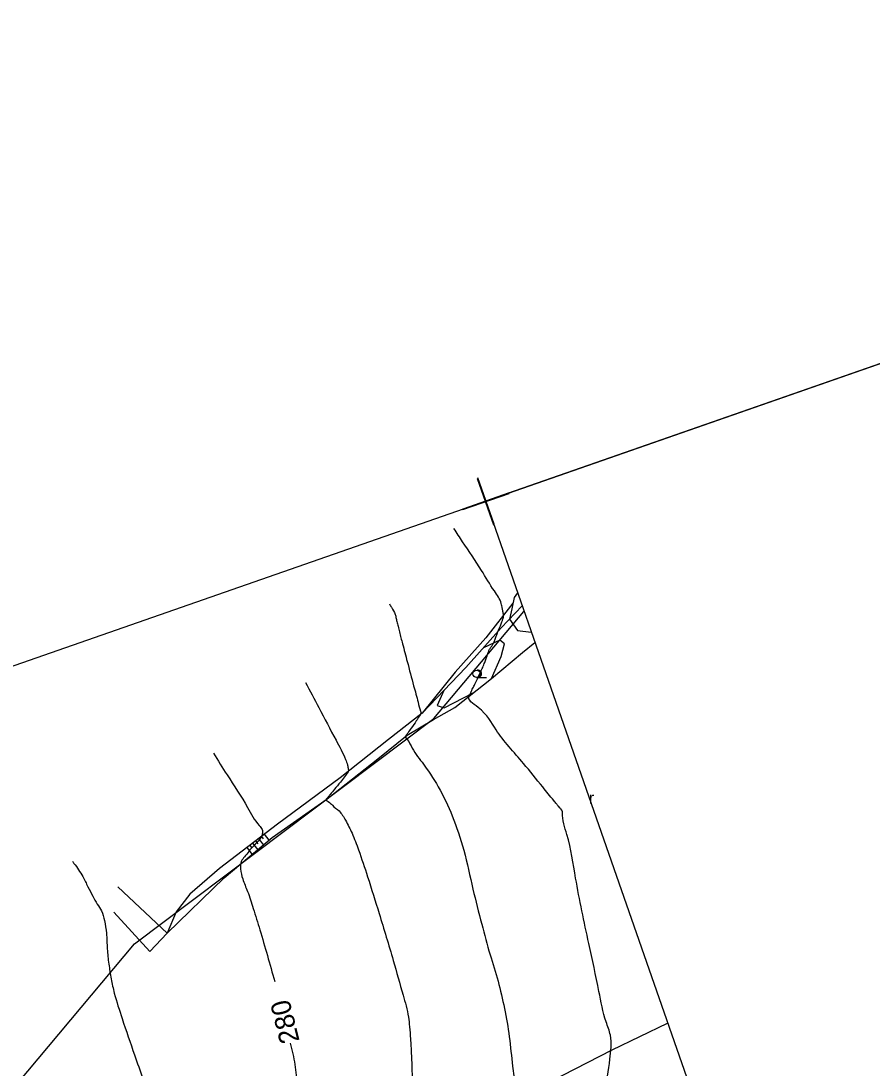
# Model space of a CAD drawing. Extents: x -477701 to -476785, y -1116511 to -1115314.
# Drawn here: x -477510.1 to -477336.7, y -1115532.3 to -1115319.1 of the extents above; entities that cross this region are included whole.
import ezdxf

# ---------------------------------------------------------------- set-up
doc = ezdxf.new("R2010")
doc.units = 0
for name, color, linetype in [('ObPÚ', 7, 'Continuous'), ('razitko', 7, 'Continuous'), ('SVK_STAT', 7, 'Continuous'), ('Vrstevnice_hlavni', 7, 'Continuous'), ('Vrstevnice_popis', 7, 'Continuous'), ('Vrstevnice_vedlejsi', 7, 'Continuous')]:
    doc.layers.add(name, color=color, linetype=linetype)

msp = doc.modelspace()

# ---------------------------------------------------------------- linework, layer by layer
at = {"layer": 'ObPÚ'}
msp.add_lwpolyline([(-477633.61, -1115693.32), (-477565.48, -1115600.75), (-477486.91, -1115507.04), (-477425.98, -1115461.11), (-477407.63, -1115439.32)], dxfattribs=at)
at = {"layer": 'razitko'}
for p, q in [((-477413.76, -1115421.73), (-477417.06, -1115412.29)), ((-477413.76, -1115421.73), (-477417.06, -1115412.29)), ((-477413.71, -1115421.55), (-477417.01, -1115412.11)), ((-477413.71, -1115421.55), (-477417.01, -1115412.11)), ((-477413.71, -1115421.55), (-477417.01, -1115412.11)), ((-477413.71, -1115421.55), (-477417.01, -1115412.11)), ((-477413.71, -1115421.55), (-477417.01, -1115412.11)), ((-477413.71, -1115421.55), (-477417.01, -1115412.11)), ((-477413.71, -1115421.55), (-477417.01, -1115412.11)), ((-477413.71, -1115421.55), (-477417.01, -1115412.11)), ((-477413.71, -1115421.55), (-477417.01, -1115412.11)), ((-477413.71, -1115421.55), (-477417.01, -1115412.11)), ((-477413.71, -1115421.55), (-477417.01, -1115412.11)), ((-477413.71, -1115421.55), (-477417.01, -1115412.11)), ((-477413.71, -1115421.55), (-477417.01, -1115412.11)), ((-477413.71, -1115421.55), (-477417.01, -1115412.11)), ((-477410.69, -1115415.37), (-477420.13, -1115418.66)), ((-477410.69, -1115415.37), (-477420.13, -1115418.66)), ((-477410.64, -1115415.18), (-477420.08, -1115418.47)), ((-477410.64, -1115415.18), (-477420.08, -1115418.47)), ((-477410.64, -1115415.18), (-477420.08, -1115418.47)), ((-477410.64, -1115415.18), (-477420.08, -1115418.47)), ((-477410.64, -1115415.18), (-477420.08, -1115418.47)), ((-477410.64, -1115415.18), (-477420.08, -1115418.47)), ((-477410.64, -1115415.18), (-477420.08, -1115418.47)), ((-477410.64, -1115415.18), (-477420.08, -1115418.47)), ((-477410.64, -1115415.18), (-477420.08, -1115418.47)), ((-477410.64, -1115415.18), (-477420.08, -1115418.47)), ((-477410.64, -1115415.18), (-477420.08, -1115418.47)), ((-477410.64, -1115415.18), (-477420.08, -1115418.47)), ((-477410.64, -1115415.18), (-477420.08, -1115418.47)), ((-477410.64, -1115415.18), (-477420.08, -1115418.47))]:
    msp.add_line(p, q, dxfattribs=at)
for points in [[(-477134.92, -1115319.05), (-476789.2, -1116310.67), (-477350.19, -1116506.26), (-477695.91, -1115514.64)], [(-477134.92, -1115319.05), (-476789.25, -1116310.52), (-477069.69, -1116408.3), (-477415.36, -1115416.83)]]:
    msp.add_lwpolyline(points, close=True, dxfattribs=at)
at = {"layer": 'SVK_STAT'}
for p, q in [((-477417.26, -1115452.77), (-477415.26, -1115452.77)), ((-477460.5, -1115484.69), (-477459.55, -1115485.94)), ((-477463.48, -1115486.97), (-477463.07, -1115487.5)), ((-477462.89, -1115486.51), (-477461.85, -1115487.87)), ((-477462.29, -1115486.06), (-477461.85, -1115486.63)), ((-477461.7, -1115485.6), (-477460.7, -1115486.9)), ((-477461.1, -1115485.15), (-477460.72, -1115485.64)), ((-477464.08, -1115487.43), (-477463, -1115488.83))]:
    msp.add_line(p, q, dxfattribs=at)
for points in [[(-477408.95, -1115435.54), (-477409.65, -1115436.47), (-477410.13, -1115438.8), (-477410.55, -1115440.88), (-477408.93, -1115443.18), (-477406.15, -1115443.58)], [(-477409.89, -1115437.63), (-477415.38, -1115444.67), (-477421.65, -1115451.69), (-477428.38, -1115460.07)], [(-477408.02, -1115438.21), (-477412.25, -1115442.69), (-477419.47, -1115450.75), (-477428.38, -1115460.07), (-477435.24, -1115465.39), (-477445.09, -1115473.25), (-477457.83, -1115482.64), (-477469.63, -1115491.69), (-477475.7, -1115496.9), (-477478.48, -1115500.48), (-477480.32, -1115504.89)], [(-477480.32, -1115504.89), (-477468.68, -1115493.6), (-477458.91, -1115485.4), (-477447.71, -1115477.47), (-477437.37, -1115469.35), (-477431.38, -1115464.51), (-477426.08, -1115461.33), (-477421.68, -1115458.86), (-477414.22, -1115452.98), (-477407.92, -1115447.67), (-477405.43, -1115445.64)], [(-477414.22, -1115452.98), (-477412.29, -1115448.52), (-477411.62, -1115445.94), (-477412.53, -1115445.21), (-477415.86, -1115446.72)], [(-477423.93, -1115455.41), (-477425.28, -1115458.5), (-477423.86, -1115458.97), (-477417.95, -1115455.92)], [(-477491.17, -1115500.56), (-477483.8, -1115508.56), (-477480.32, -1115504.89), (-477490.33, -1115495.45)], [(-477427.86, -1115563.62), (-477422.06, -1115550.46), (-477409.86, -1115539), (-477389.68, -1115528.61), (-477378.39, -1115523.19)]]:
    msp.add_lwpolyline(points, dxfattribs=at)
msp.add_circle((-477417.26, -1115452.02), 0.75, dxfattribs=at)
msp.add_arc((-477417.01, -1115452.02), 0.75, 260.4059, 99.5941, dxfattribs=at)
at = {"layer": 'Vrstevnice_hlavni'}
for points in [[(-477470.88, -1115468.18), (-477468.09, -1115472.63), (-477463.92, -1115479.23), (-477461.54, -1115482.94), (-477460.94, -1115483.75), (-477460.93, -1115484.71), (-477461.5, -1115485.8), (-477462.67, -1115487.04), (-477463.67, -1115488.2), (-477464.52, -1115489.28), (-477465.21, -1115490.27), (-477465.34, -1115491.78), (-477464.91, -1115493.81), (-477463.92, -1115496.35), (-477462.76, -1115499.8), (-477461.42, -1115504.15), (-477458.39, -1115514.68)], [(-477455.25, -1115527.25), (-477454.28, -1115531.61), (-477453.93, -1115535.98), (-477453.71, -1115542.53), (-477453.62, -1115551.27), (-477452.88, -1115560.5), (-477451.47, -1115570.23), (-477449.42, -1115580.46), (-477447.7, -1115588.21), (-477446.32, -1115593.47), (-477445.28, -1115596.25), (-477444.5, -1115598.3), (-477443.99, -1115599.63), (-477443.73, -1115600.22), (-477443.33, -1115600.85), (-477442.79, -1115601.52), (-477442.09, -1115602.23), (-477441.43, -1115602.82), (-477440.8, -1115603.32), (-477440.21, -1115603.7), (-477438, -1115605.12), (-477434.18, -1115607.56), (-477428.74, -1115611.03), (-477424.51, -1115613.85), (-477421.48, -1115616.01), (-477419.66, -1115617.52), (-477417.5, -1115619.22), (-477415.02, -1115621.12), (-477412.2, -1115623.21), (-477409.53, -1115625.29), (-477407, -1115627.35), (-477404.6, -1115629.39), (-477402.88, -1115630.91), (-477401.82, -1115631.93), (-477401.44, -1115632.44), (-477401.06, -1115632.84), (-477400.71, -1115633.14), (-477400.36, -1115633.34), (-477398.97, -1115634.31), (-477396.51, -1115636.06), (-477393.01, -1115638.58), (-477389.76, -1115640.78), (-477386.78, -1115642.66), (-477384.06, -1115644.2), (-477382.21, -1115645.24), (-477381.24, -1115645.78), (-477381.13, -1115645.8), (-477380.99, -1115645.83), (-477380.81, -1115645.87), (-477380.58, -1115645.91), (-477380.45, -1115646.15), (-477380.4, -1115646.61), (-477380.44, -1115647.28), (-477380.32, -1115647.94), (-477380.04, -1115648.6), (-477379.6, -1115649.25), (-477378.81, -1115650.19), (-477377.67, -1115651.41), (-477376.18, -1115652.91), (-477373.49, -1115655.96), (-477369.58, -1115660.54), (-477364.46, -1115666.67), (-477360.7, -1115671.04), (-477358.31, -1115673.66), (-477357.28, -1115674.52), (-477356.2, -1115675.6), (-477355.08, -1115676.92), (-477353.91, -1115678.46), (-477352.08, -1115681.9), (-477349.57, -1115687.23), (-477346.39, -1115694.45), (-477343.98, -1115699.91), (-477342.34, -1115703.6), (-477341.47, -1115705.52), (-477340.85, -1115706.87), (-477340.49, -1115707.65), (-477340.39, -1115707.86), (-477340.31, -1115708.31), (-477340.25, -1115708.99), (-477340.22, -1115709.9), (-477340.21, -1115710.84), (-477340.24, -1115711.8), (-477340.29, -1115712.78), (-477340.32, -1115714.53), (-477340.31, -1115717.03), (-477340.27, -1115720.29), (-477340.21, -1115722.74), (-477340.12, -1115724.39), (-477339.92, -1115726.07)]]:
    msp.add_spline(points, degree=3, dxfattribs=at)
at = {"layer": 'Vrstevnice_vedlejsi'}
for points in [[(-477394.42, -1115506.95), (-477397.1, -1115493.65), (-477398.88, -1115484.77), (-477399.77, -1115480.32), (-477399.77, -1115480.28), (-477399.78, -1115480.23), (-477399.79, -1115480.17), (-477399.8, -1115480.08), (-477399.83, -1115480), (-477399.87, -1115479.9), (-477399.93, -1115479.81), (-477399.98, -1115479.74), (-477400.01, -1115479.7), (-477400.02, -1115479.68), (-477400.03, -1115479.67), (-477400.05, -1115479.65), (-477400.08, -1115479.62), (-477400.12, -1115479.57), (-477400.19, -1115479.5), (-477400.28, -1115479.4), (-477400.54, -1115479.09), (-477400.96, -1115478.57), (-477401.56, -1115477.84), (-477403.81, -1115475.08), (-477407.72, -1115470.29), (-477413.29, -1115463.46), (-477416.97, -1115458.87), (-477418.77, -1115456.51), (-477418.69, -1115456.39), (-477418.61, -1115456.26), (-477418.55, -1115456.13), (-477418.5, -1115456.01), (-477418.43, -1115455.85), (-477418.35, -1115455.66), (-477418.26, -1115455.44), (-477418.02, -1115454.93), (-477417.63, -1115454.14), (-477417.11, -1115453.06), (-477416.61, -1115452), (-477416.14, -1115450.97), (-477415.71, -1115449.96), (-477415.37, -1115449.1), (-477415.12, -1115448.38), (-477414.97, -1115447.81), (-477414.75, -1115447.27), (-477414.46, -1115446.75), (-477414.11, -1115446.26), (-477413.78, -1115445.67), (-477413.47, -1115444.98), (-477413.19, -1115444.2), (-477412.99, -1115443.64), (-477412.86, -1115443.28), (-477412.8, -1115443.14), (-477412.66, -1115442.79), (-477412.43, -1115442.23), (-477412.12, -1115441.45), (-477411.92, -1115440.87), (-477411.81, -1115440.49), (-477411.82, -1115440.3), (-477411.82, -1115440.11), (-477411.82, -1115439.93), (-477411.83, -1115439.76), (-477411.9, -1115439.33), (-477412.04, -1115438.66), (-477412.24, -1115437.73), (-477413.66, -1115435.16), (-477416.28, -1115430.96), (-477420.12, -1115425.13), (-477421.89, -1115422.43)], [(-477435.04, -1115437.77), (-477434.6, -1115438.49), (-477433.83, -1115439.94), (-477433.69, -1115440.58), (-477433.5, -1115441.39), (-477433.26, -1115442.36), (-477432.99, -1115443.51), (-477432.36, -1115445.9), (-477431.4, -1115449.55), (-477430.09, -1115454.46), (-477429.19, -1115457.83), (-477428.69, -1115459.64), (-477428.61, -1115459.91), (-477428.9, -1115460.57), (-477429.56, -1115461.64), (-477430.59, -1115463.1), (-477431.31, -1115464.11), (-477431.71, -1115464.68), (-477431.79, -1115464.79), (-477431.83, -1115464.89), (-477431.82, -1115464.97), (-477431.76, -1115465.03), (-477430.62, -1115466.73), (-477428.39, -1115470.06), (-477425.08, -1115475.03), (-477422.24, -1115480.99), (-477419.89, -1115487.95), (-477418.02, -1115495.9), (-477416.23, -1115503), (-477414.53, -1115509.24), (-477412.91, -1115514.62), (-477411.61, -1115520.19), (-477410.62, -1115525.96), (-477409.95, -1115531.92), (-477409.48, -1115535.97), (-477409.23, -1115538.13), (-477409.19, -1115538.38), (-477409.19, -1115538.71), (-477409.24, -1115539.11), (-477409.33, -1115539.59), (-477409.7, -1115541.71), (-477410.34, -1115545.46), (-477411.26, -1115550.86), (-477411.78, -1115555.26), (-477411.93, -1115558.66), (-477411.68, -1115561.07), (-477411.47, -1115563.24), (-477411.29, -1115565.17), (-477411.15, -1115566.85), (-477409.83, -1115570.16), (-477407.33, -1115575.1), (-477403.67, -1115581.68), (-477400.28, -1115587.03), (-477397.17, -1115591.16), (-477394.33, -1115594.06), (-477392.48, -1115596.11), (-477391.61, -1115597.31), (-477391.73, -1115597.66), (-477391.65, -1115597.92), (-477391.35, -1115598.09), (-477390.86, -1115598.18), (-477390.36, -1115598.34), (-477389.87, -1115598.57), (-477389.39, -1115598.86), (-477388.15, -1115599.09), (-477386.16, -1115599.26), (-477383.42, -1115599.36), (-477381.5, -1115599.47), (-477380.41, -1115599.58), (-477380.14, -1115599.7), (-477379.5, -1115600.08), (-477378.5, -1115600.73), (-477377.13, -1115601.64), (-477374.84, -1115602.71), (-477371.62, -1115603.92), (-477367.48, -1115605.29), (-477364.55, -1115606.35), (-477362.82, -1115607.12), (-477362.31, -1115607.57), (-477360.03, -1115608.44), (-477356, -1115609.72), (-477350.21, -1115611.41), (-477346.29, -1115612.72), (-477344.25, -1115613.66), (-477344.09, -1115614.22), (-477343.24, -1115615.37), (-477341.71, -1115617.12)], [(-477452.12, -1115453.79), (-477449.4, -1115458.89), (-477445.9, -1115465.56), (-477443.96, -1115469.47), (-477443.58, -1115470.61), (-477443.4, -1115471.46), (-477443.41, -1115472.03), (-477443.61, -1115472.32), (-477444.15, -1115473), (-477445.02, -1115474.08), (-477446.22, -1115475.55), (-477447.08, -1115476.59), (-477447.58, -1115477.2), (-477447.73, -1115477.38), (-477447.84, -1115477.51), (-477447.91, -1115477.59), (-477447.93, -1115477.62), (-477447.51, -1115478.03), (-477446.63, -1115478.81), (-477445.29, -1115479.97), (-477443.96, -1115481.87), (-477442.63, -1115484.51), (-477441.32, -1115487.9), (-477439.48, -1115493.35), (-477437.12, -1115500.86), (-477434.24, -1115510.43), (-477432.25, -1115517.46), (-477431.15, -1115521.95), (-477430.93, -1115523.91), (-477430.73, -1115526.39), (-477430.57, -1115529.4), (-477430.43, -1115532.94), (-477430.32, -1115537.32), (-477430.24, -1115542.56), (-477430.18, -1115548.66), (-477429.73, -1115553.34), (-477428.89, -1115556.61), (-477427.65, -1115558.48), (-477426.79, -1115560.08), (-477426.31, -1115561.43), (-477426.2, -1115562.52), (-477426.01, -1115564.52), (-477425.75, -1115567.44), (-477425.41, -1115571.28), (-477424.55, -1115574.97), (-477423.17, -1115578.52), (-477421.27, -1115581.94), (-477419.91, -1115585.25), (-477419.09, -1115588.48), (-477418.81, -1115591.6), (-477417.29, -1115595.06), (-477414.52, -1115598.84), (-477410.51, -1115602.95), (-477407.21, -1115606), (-477404.64, -1115607.98), (-477402.79, -1115608.89), (-477401.47, -1115609.56), (-477400.68, -1115609.99), (-477400.43, -1115610.17), (-477400.25, -1115610.33), (-477400.14, -1115610.47), (-477400.09, -1115610.6), (-477400, -1115610.7), (-477399.85, -1115610.79), (-477399.64, -1115610.85), (-477399.22, -1115611.02), (-477398.57, -1115611.29), (-477397.69, -1115611.67), (-477394.57, -1115613.61), (-477389.21, -1115617.12), (-477381.59, -1115622.2), (-477376.05, -1115625.74), (-477372.56, -1115627.75), (-477371.15, -1115628.22), (-477369.14, -1115629.47), (-477366.54, -1115631.51), (-477363.35, -1115634.33), (-477361.05, -1115636.26), (-477359.64, -1115637.3), (-477359.13, -1115637.45), (-477358.6, -1115638.16), (-477358.08, -1115639.43), (-477357.54, -1115641.25), (-477357.19, -1115642.51), (-477357.01, -1115643.18), (-477357.01, -1115643.28), (-477357, -1115643.37), (-477356.98, -1115643.44)], [(-477499.59, -1115490.21), (-477499.26, -1115490.64), (-477497.49, -1115493.31), (-477496.42, -1115495.44), (-477495.43, -1115497.32), (-477494.51, -1115498.94), (-477493.67, -1115500.31), (-477493.05, -1115502.28), (-477492.66, -1115504.87), (-477492.49, -1115508.06), (-477492.17, -1115511.16), (-477491.69, -1115514.17), (-477491.05, -1115517.08), (-477489.46, -1115522.25), (-477486.94, -1115529.66), (-477483.47, -1115539.32), (-477480.93, -1115546.76), (-477479.33, -1115551.99), (-477478.67, -1115555), (-477478.22, -1115557.22), (-477478, -1115558.67), (-477477.99, -1115559.33), (-477477.93, -1115560.04), (-477477.83, -1115560.78), (-477477.67, -1115561.56), (-477477.5, -1115562.26), (-477477.31, -1115562.88), (-477477.11, -1115563.42), (-477476.07, -1115567.85), (-477474.19, -1115576.17), (-477471.47, -1115588.39), (-477469.23, -1115596.71), (-477467.47, -1115601.13), (-477466.19, -1115601.67), (-477465.13, -1115602.11), (-477464.28, -1115602.47), (-477463.66, -1115602.73), (-477462.42, -1115604.03), (-477460.58, -1115606.35), (-477458.13, -1115609.71), (-477456.68, -1115612.47), (-477456.22, -1115614.63), (-477456.75, -1115616.21), (-477455.45, -1115618.41), (-477452.33, -1115621.25), (-477447.38, -1115624.73), (-477443.98, -1115627.16), (-477442.12, -1115628.54), (-477441.8, -1115628.88), (-477441.39, -1115629.26), (-477440.88, -1115629.68), (-477440.27, -1115630.16), (-477439.3, -1115630.94), (-477437.96, -1115632.04), (-477436.26, -1115633.44), (-477434.36, -1115634.95), (-477432.25, -1115636.57), (-477429.94, -1115638.28), (-477425.33, -1115642.3), (-477418.42, -1115648.61), (-477409.21, -1115657.23), (-477402.26, -1115663.53), (-477397.58, -1115667.5), (-477395.15, -1115669.16), (-477392.97, -1115671.04), (-477391.05, -1115673.15), (-477389.37, -1115675.49), (-477388.15, -1115677.17), (-477387.4, -1115678.2), (-477387.11, -1115678.59), (-477386.85, -1115678.9), (-477386.63, -1115679.14), (-477386.43, -1115679.32), (-477386.2, -1115679.62), (-477385.93, -1115680.04), (-477385.62, -1115680.59), (-477384.28, -1115682.52), (-477381.93, -1115685.84), (-477378.55, -1115690.54), (-477376.1, -1115694.23), (-477374.58, -1115696.9)], [(-477355.67, -1115588.35), (-477365.8, -1115581.97), (-477380.23, -1115572.57), (-477389.9, -1115565.45), (-477392.63, -1115563.37), (-477393.83, -1115562.14), (-477394.35, -1115561.43), (-477394.81, -1115560.63), (-477395.08, -1115559.37), (-477394.96, -1115558.09), (-477394.4, -1115553.39), (-477393.13, -1115546.5), (-477391.15, -1115537.44), (-477390.12, -1115530.49), (-477390.03, -1115525.66), (-477390.89, -1115522.95), (-477392.35, -1115516.72), (-477394.42, -1115506.95)]]:
    msp.add_spline(points, degree=3, dxfattribs=at)

# ---------------------------------------------------------------- texts
at = {"layer": 'SVK_STAT'}
msp.add_text('r', height=2.4, dxfattribs=at).set_placement((-477394.4, -1115478.5))
at = {"layer": 'Vrstevnice_popis'}
msp.add_text(' 280 ', height=4, rotation=104.0136, dxfattribs=at).set_placement((-477452.94, -1115528.24))

doc.saveas('drawing.dxf')
